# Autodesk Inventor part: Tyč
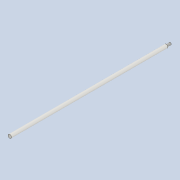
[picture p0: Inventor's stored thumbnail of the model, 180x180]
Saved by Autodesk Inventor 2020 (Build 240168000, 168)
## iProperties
Created: 2025-03
Part Number: Tyč
Material: Ocel
Document SubType Name: Modeling
Designer: doma
Mass: 679.733 g
Surface Area: 236.326 cm^2
Volume: 86.5901 cm^3
Density: 7.85 g/cm^3
Appearance: Ocel
Author: doma
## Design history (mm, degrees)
sketch "Náčrt1"
  geometry: C1 r 7.5 at (0, 0); 1 further point
  constraints: 1 centre point, 1 coincident
  dimensions: "d0" = 15 diameter of C1
extrude "Vysunutí1" new body sketch "Náčrt1" distance "d1" = 700; taper "d2" = 0 deg
sketch "Náčrt2"
  geometry: C1 r 5 at (0, 0); C2 r 7.5 at (0, 0) reference; 1 further point
  constraints: 1 centre point, 1 coincident
  dimensions: "d3" = 10 diameter of C1
extrude "Vysunutí2" cut sketch "Náčrt2" distance "d4" = 18; taper "d5" = 0 deg
feature "Závit1" dims "d6" = 18, "d7" = 0
node "Těleso1"
